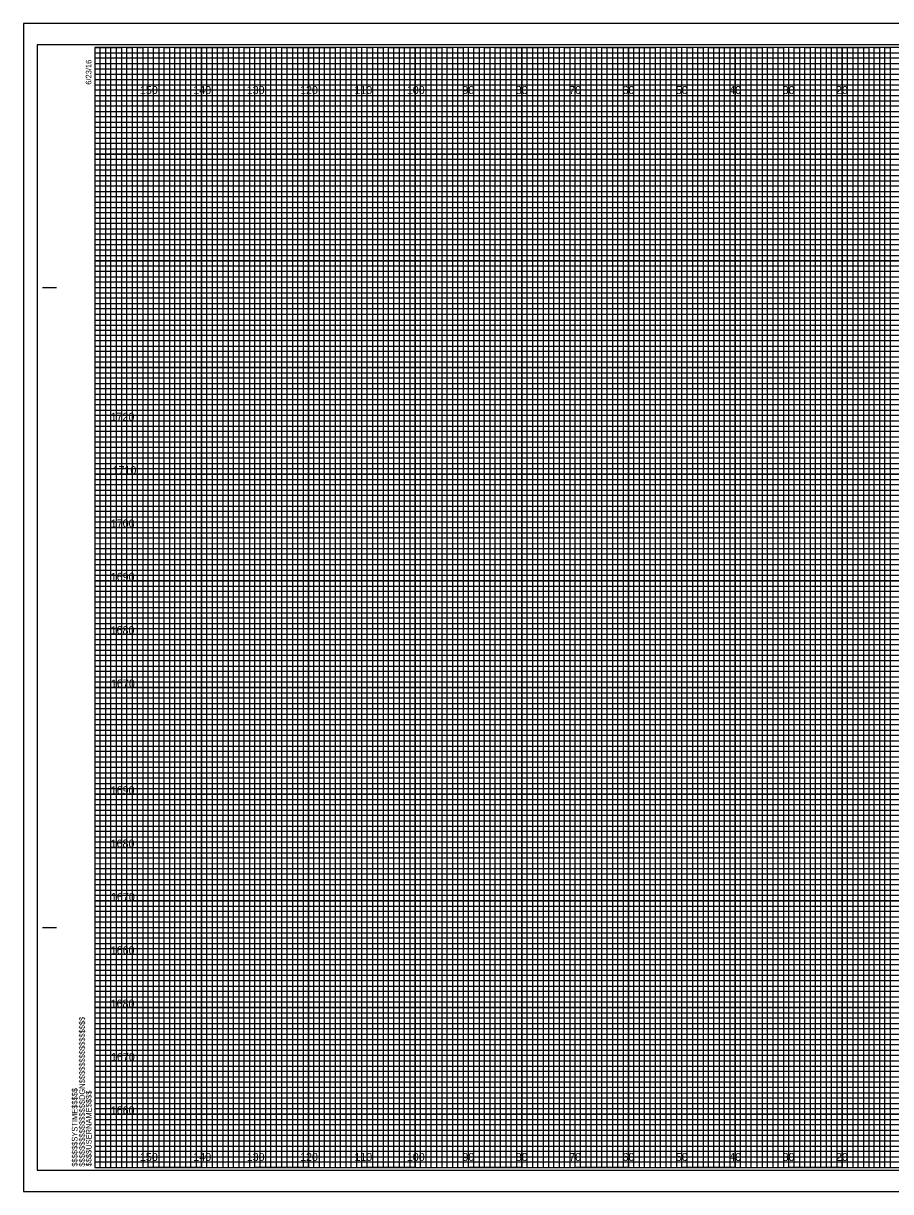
# Model space of a CAD drawing. Extents: x 185 to 522, y -7 to 872.
# Drawn here: x 184.8 to 347.3, y -6.5 to 212.5 of the extents above; entities that cross this region are included whole.
import ezdxf

# ---------------------------------------------------------------- set-up
doc = ezdxf.new("R2010")
doc.units = 0
for name, color, linetype in [('Raster_Level_0', 7, 'Continuous'), ('Scratch_Level_3', 7, 'Continuous'), ('Sheet Cross Section CELL', 7, 'Continuous'), ('Sheet Cross Section Grid Major CELL', 7, 'Continuous'), ('Sheet Cross Section Grid Middle CELL', 7, 'Continuous'), ('Sheet Cross Section Grid Minor 1 CELL', 7, 'Continuous'), ('Sheet Cross Section Grid Minor 2 CELL', 7, 'Continuous'), ('Sheet Cutting Line CELL', 7, 'Continuous'), ('Sheet DOT Grid CELL', 7, 'Continuous'), ('Sheet Plot Border Inside CELL', 7, 'Continuous'), ('Sheet Plot Border Outside CELL', 7, 'Continuous')]:
    doc.layers.add(name, color=color, linetype=linetype)

msp = doc.modelspace()

# ---------------------------------------------------------------- linework, layer by layer
at = {"layer": 'Sheet Cross Section CELL'}
for p, q in [((188.44, 162.95), (190.94, 162.95)), ((188.54, 162.95), (191.04, 162.95)), ((188.44, 42.95), (190.94, 42.95)), ((188.54, 42.95), (191.04, 42.95)), ((198.24, -2.05), (198.24, -2.05)), ((198.24, -2.05), (198.24, -2.05)), ((198.24, -2.05), (198.24, -2.05)), ((198.24, -2.05), (198.24, -2.05)), ((198.24, -2.05), (198.24, -2.05)), ((198.24, -2.05), (198.24, -2.05)), ((198.24, -2.05), (198.24, -2.05))]:
    msp.add_line(p, q, dxfattribs=at)
msp.add_lwpolyline([(518.24, 207.95), (198.24, 207.95), (198.24, -2.05), (518.24, -2.05)], close=True, dxfattribs=at)
at = {"layer": 'Sheet Cross Section Grid Major CELL'}
for p, q in [((208.24, 207.95), (198.24, 207.95)), ((208.24, -2.05), (208.24, 207.95)), ((228.24, 207.95), (218.24, 207.95)), ((218.24, 207.95), (218.24, -2.05)), ((228.24, -2.05), (228.24, 207.95)), ((248.24, 207.95), (238.24, 207.95)), ((238.24, 207.95), (238.24, -2.05)), ((248.24, -2.05), (248.24, 207.95)), ((268.24, 207.95), (258.24, 207.95)), ((258.24, 207.95), (258.24, -2.05)), ((268.24, -2.05), (268.24, 207.95)), ((288.24, 207.95), (278.24, 207.95)), ((278.24, 207.95), (278.24, -2.05)), ((288.24, -2.05), (288.24, 207.95)), ((308.24, 207.95), (298.24, 207.95)), ((298.24, 207.95), (298.24, -2.05)), ((308.24, -2.05), (308.24, 207.95)), ((328.24, 207.95), (318.24, 207.95)), ((318.24, 207.95), (318.24, -2.05)), ((328.24, -2.05), (328.24, 207.95)), ((348.24, 207.95), (338.24, 207.95)), ((338.24, 207.95), (338.24, -2.05)), ((218.24, -2.05), (208.24, -2.05)), ((238.24, -2.05), (228.24, -2.05)), ((258.24, -2.05), (248.24, -2.05)), ((278.24, -2.05), (268.24, -2.05)), ((298.24, -2.05), (288.24, -2.05)), ((318.24, -2.05), (308.24, -2.05)), ((338.24, -2.05), (328.24, -2.05))]:
    msp.add_line(p, q, dxfattribs=at)
for points in [[(198.24, 197.95), (518.24, 197.95), (518.24, 187.95), (198.24, 187.95)], [(198.24, 177.95), (518.24, 177.95), (518.24, 167.95), (198.24, 167.95)], [(198.24, 157.95), (518.24, 157.95), (518.24, 147.95), (198.24, 147.95)], [(198.24, 137.95), (518.24, 137.95), (518.24, 127.95), (198.24, 127.95)], [(198.24, 117.95), (518.24, 117.95), (518.24, 107.95), (198.24, 107.95)], [(198.24, 97.95), (518.24, 97.95), (518.24, 87.95), (198.24, 87.95)], [(198.24, 77.95), (518.24, 77.95), (518.24, 67.95), (198.24, 67.95)], [(198.24, 57.95), (518.24, 57.95), (518.24, 47.95), (198.24, 47.95)], [(198.24, 37.95), (518.24, 37.95), (518.24, 27.95), (198.24, 27.95)], [(198.24, 17.95), (518.24, 17.95), (518.24, 7.95), (198.24, 7.95)]]:
    msp.add_lwpolyline(points, dxfattribs=at)
at = {"layer": 'Sheet Cross Section Grid Middle CELL'}
for points in [[(198.24, 207.95), (203.24, 207.95), (203.24, -2.05), (213.24, -2.05), (213.24, 207.95), (223.24, 207.95), (223.24, -2.05), (233.24, -2.05), (233.24, 207.95), (243.24, 207.95), (243.24, -2.05), (253.24, -2.05), (253.24, 207.95), (263.24, 207.95), (263.24, -2.05), (273.24, -2.05), (273.24, 207.95), (283.24, 207.95), (283.24, -2.05), (293.24, -2.05), (293.24, 207.95), (303.24, 207.95), (303.24, -2.05), (313.24, -2.05), (313.24, 207.95), (323.24, 207.95), (323.24, -2.05), (333.24, -2.05), (333.24, 207.95), (343.24, 207.95), (343.24, -2.05), (353.24, -2.05)], [(198.24, 202.95), (473.24, 202.95)], [(198.24, 182.95), (518.24, 182.95), (518.24, 192.95), (198.24, 192.95)], [(198.24, 162.95), (518.24, 162.95), (518.24, 172.95), (198.24, 172.95)], [(198.24, 142.95), (518.24, 142.95), (518.24, 152.95), (198.24, 152.95)], [(198.24, 122.95), (518.24, 122.95), (518.24, 132.95), (198.24, 132.95)], [(198.24, 102.95), (518.24, 102.95), (518.24, 112.95), (198.24, 112.95)], [(198.24, 82.95), (518.24, 82.95), (518.24, 92.95), (198.24, 92.95)], [(198.24, 62.95), (518.24, 62.95), (518.24, 72.95), (198.24, 72.95)], [(198.24, 42.95), (518.24, 42.95), (518.24, 52.95), (198.24, 52.95)], [(198.24, 22.95), (518.24, 22.95), (518.24, 32.95), (198.24, 32.95)], [(198.24, 2.95), (518.24, 2.95), (518.24, 12.95), (198.24, 12.95)]]:
    msp.add_lwpolyline(points, dxfattribs=at)
at = {"layer": 'Sheet Cross Section Grid Minor 1 CELL'}
for p, q in [((198.24, 206.95), (458.24, 206.95)), ((458.24, 205.93), (198.24, 205.93)), ((198.24, 205.93), (198.24, 204.95)), ((198.24, 204.95), (458.24, 204.95)), ((458.24, 203.84), (198.24, 203.84)), ((198.24, 203.84), (198.24, 201.95)), ((198.24, 201.95), (518.24, 201.95))]:
    msp.add_line(p, q, dxfattribs=at)
for points in [[(198.24, 200.95), (468.24, 200.95), (518.24, 200.95), (518.24, 199.95), (198.24, 199.95)], [(198.24, 198.95), (518.24, 198.95), (518.24, 196.95), (198.24, 196.95)], [(198.24, 195.95), (518.24, 195.95), (518.24, 194.95), (198.24, 194.93)], [(198.24, 193.95), (518.24, 193.95), (518.24, 191.95), (198.24, 191.95)], [(198.24, 190.95), (518.24, 190.95), (518.24, 189.95), (198.24, 189.95)], [(198.24, 188.95), (518.24, 188.95), (518.24, 186.95), (198.24, 186.95)], [(198.24, 185.95), (518.24, 185.95), (518.24, 184.95), (198.24, 184.95)], [(198.24, 183.95), (518.24, 183.95), (518.24, 181.95), (198.24, 181.95)], [(198.24, 180.95), (518.24, 180.95), (518.24, 179.95), (198.24, 179.95)], [(198.24, 178.95), (518.24, 178.95), (518.24, 176.95), (198.24, 176.95)], [(198.24, 175.95), (518.24, 175.95), (518.24, 174.95), (198.24, 174.95)], [(198.24, 173.95), (518.24, 173.95), (518.24, 171.9), (518.24, 170.95), (518.24, 169.95), (198.24, 169.95)], [(198.24, 171.95), (518.24, 171.95), (518.24, 170.95), (198.24, 170.95)], [(198.24, 168.95), (518.24, 168.95), (518.24, 166.95), (198.24, 166.98)], [(198.24, 166.98), (518.24, 166.95), (518.24, 165.95), (198.24, 165.95)], [(198.24, 164.95), (518.24, 164.95), (518.24, 163.95), (198.24, 163.95)], [(198.24, 161.95), (518.24, 161.95), (518.24, 160.95), (198.24, 160.95)], [(198.24, 159.95), (518.24, 159.95), (518.24, 158.95), (198.24, 158.95)], [(198.17, 156.84), (518.24, 156.84), (518.24, 155.83), (198.17, 155.83)], [(198.24, 154.95), (518.24, 154.95), (518.24, 153.95), (198.24, 153.95)], [(198.24, 151.95), (518.24, 151.95), (518.24, 150.95), (198.24, 150.95)], [(198.24, 149.95), (518.24, 149.95), (518.24, 148.95), (198.24, 148.95)], [(198.24, 146.95), (518.24, 146.95), (518.24, 145.95), (198.24, 145.95)], [(198.24, 144.95), (518.24, 144.95), (518.24, 143.95), (198.24, 143.95)], [(198.24, 141.95), (518.24, 141.95), (518.24, 140.95), (198.24, 140.95)], [(198.24, 139.95), (518.24, 139.95), (518.24, 138.95), (198.24, 138.95)], [(198.24, 136.95), (518.24, 136.95), (518.23, 135.93), (198.24, 135.95)], [(198.24, 134.95), (518.24, 134.95), (518.24, 133.95), (198.24, 133.95)], [(198.24, 131.95), (518.24, 131.95), (518.24, 130.95), (198.24, 130.95)], [(198.24, 129.95), (518.24, 129.95), (518.24, 128.95), (198.24, 128.95)], [(198.24, 126.95), (518.24, 126.95), (518.24, 125.95), (198.24, 125.95)], [(198.24, 124.95), (518.24, 124.95), (518.24, 123.95), (198.24, 123.95)], [(198.24, 121.95), (518.24, 121.95), (518.24, 120.95), (198.24, 120.95)], [(198.24, 119.95), (518.24, 119.95), (518.24, 118.95), (198.24, 118.95)], [(198.24, 116.95), (518.24, 116.95), (518.24, 115.95), (198.24, 115.95)], [(198.24, 114.94), (518.31, 114.86), (518.24, 113.95), (198.24, 113.95)], [(198.24, 111.95), (518.24, 111.95), (518.24, 110.95), (198.24, 110.95)], [(198.24, 109.95), (518.24, 109.95), (518.24, 108.95), (198.24, 108.95)], [(198.24, 106.95), (518.24, 106.95), (518.24, 105.95), (198.24, 105.95)], [(198.24, 104.95), (518.24, 104.95), (518.24, 103.95), (198.24, 103.95)], [(198.24, 101.95), (518.24, 101.95), (518.24, 100.95), (198.24, 100.95)], [(198.24, 99.95), (518.24, 99.95), (518.24, 98.95), (198.24, 98.95)], [(198.24, 96.95), (518.24, 96.95), (518.24, 95.95), (198.24, 95.95)], [(198.24, 94.95), (518.24, 94.95), (518.24, 93.95), (198.24, 93.95)], [(198.24, 91.95), (518.24, 91.95), (518.24, 90.95), (198.24, 90.95)], [(198.24, 89.95), (518.24, 89.95), (518.24, 88.95), (198.24, 88.95)], [(198.24, 86.95), (518.24, 86.95), (518.24, 85.95), (198.24, 85.95)], [(198.24, 84.95), (518.24, 84.95), (518.24, 83.95), (198.24, 83.95)], [(198.24, 81.95), (518.24, 81.95), (518.24, 80.95), (198.24, 80.95)], [(198.24, 79.95), (518.24, 79.95), (518.24, 78.95), (198.24, 78.95)], [(198.24, 76.95), (518.24, 76.95), (518.23, 75.93), (198.24, 75.95)], [(198.24, 74.95), (518.24, 74.95), (518.24, 73.95), (198.24, 73.95)], [(198.24, 71.95), (518.24, 71.95), (518.24, 70.95), (198.24, 70.95)], [(198.24, 69.95), (518.24, 69.95), (518.24, 68.95), (198.24, 68.95)], [(198.24, 66.95), (518.24, 66.95), (518.24, 65.95), (198.24, 65.95)], [(198.24, 64.95), (518.24, 64.95), (518.24, 63.95), (198.24, 63.95)], [(198.24, 61.95), (518.24, 61.95), (518.24, 60.95), (198.24, 60.95)], [(198.24, 59.95), (518.24, 59.95), (518.24, 58.95), (198.24, 58.95)], [(198.24, 56.95), (518.24, 56.95), (518.24, 55.95), (198.24, 55.95)], [(198.24, 54.94), (518.31, 54.86), (518.24, 53.95), (198.24, 53.95)], [(198.24, 51.95), (518.24, 51.95), (518.24, 50.95), (198.24, 50.95)], [(198.24, 49.95), (518.24, 49.95), (518.24, 48.95), (198.24, 48.95)], [(198.24, 46.95), (518.24, 46.95), (518.24, 45.95), (198.24, 45.95)], [(198.24, 44.95), (518.24, 44.95), (518.24, 43.95), (198.24, 43.95)], [(198.24, 41.95), (518.24, 41.95), (518.24, 40.95), (198.24, 40.95)], [(198.24, 39.95), (518.24, 39.95), (518.24, 38.95), (198.24, 38.95)], [(198.24, 36.95), (518.24, 36.95), (518.24, 35.95), (198.24, 35.95)], [(198.24, 34.95), (518.24, 34.95), (518.24, 33.95), (198.24, 33.95)], [(198.24, 31.95), (518.24, 31.95), (518.24, 30.95), (198.24, 30.95)], [(198.24, 29.95), (518.24, 29.95), (518.24, 28.95), (198.24, 28.95)], [(198.24, 26.95), (518.24, 26.95), (518.24, 25.95), (198.24, 25.95)], [(198.24, 24.95), (518.24, 24.95), (518.24, 23.95), (198.24, 23.95)], [(198.24, 21.95), (518.24, 21.95), (518.24, 20.95), (198.24, 20.95)], [(198.24, 19.95), (518.24, 19.95), (518.24, 18.95), (198.24, 18.95)], [(198.24, 16.95), (518.24, 16.95), (518.24, 15.95), (198.24, 15.95)], [(198.24, 14.95), (518.24, 14.95), (518.24, 13.95), (198.24, 13.95)], [(198.24, 11.95), (518.24, 11.95), (518.24, 10.95), (198.24, 10.95)], [(198.24, 9.95), (518.24, 9.95), (518.24, 8.95), (198.24, 8.95)], [(198.24, 6.95), (518.24, 6.95), (518.24, 5.95), (198.24, 5.95)], [(198.24, 4.95), (518.24, 4.95), (518.24, 3.95), (198.24, 3.95)], [(198.24, 1.95), (518.24, 1.95), (518.24, 0.95), (198.24, 0.95)], [(198.24, -0.05), (518.24, -0.05), (518.24, -1.05), (198.24, -1.05)]]:
    msp.add_lwpolyline(points, dxfattribs=at)
at = {"layer": 'Sheet Cross Section Grid Minor 2 CELL'}
for points in [[(198.24, -2.05), (199.24, -2.05), (199.24, 207.95), (200.24, 207.95), (200.24, -2.05)], [(200.24, -2.05), (201.24, -2.05), (201.24, 207.95), (202.24, 207.95), (202.24, -2.05)], [(203.24, -2.05), (204.24, -2.05), (204.24, 207.95), (205.24, 207.95), (205.24, -2.05)], [(205.24, -2.05), (206.24, -2.05), (206.24, 207.95), (207.24, 207.95), (207.24, -2.05)], [(208.24, -2.05), (209.24, -2.05), (209.24, 207.95), (210.24, 207.95), (210.24, -2.05)], [(210.24, -2.05), (211.24, -2.05), (211.24, 207.95), (212.24, 207.95), (212.24, -2.05)], [(213.24, -2.05), (214.24, -2.05), (214.24, 207.95), (215.24, 207.95), (215.24, -2.05)], [(215.24, -2.05), (216.24, -2.05), (216.24, 207.95), (217.24, 207.95), (217.24, -2.05)], [(218.24, -2.05), (219.24, -2.05), (219.24, 207.95), (220.24, 207.95), (220.24, -2.05)], [(220.24, -2.05), (221.24, -2.05), (221.24, 207.95), (222.24, 207.95), (222.24, -2.05)], [(223.24, -2.05), (224.24, -2.05), (224.24, 207.95), (225.24, 207.95), (225.24, -2.05)], [(225.24, -2.05), (226.24, -2.05), (226.24, 207.95), (227.24, 207.95), (227.24, -2.05)], [(228.24, -2.05), (229.24, -2.05), (229.24, 207.95), (230.24, 207.95), (230.24, -2.05)], [(230.24, -2.05), (231.24, -2.05), (231.24, 207.95), (232.24, 207.95), (232.24, -2.05)], [(233.24, -2.05), (234.24, -2.05), (234.24, 207.95), (235.24, 207.95), (235.24, -2.05)], [(235.24, -2.05), (236.24, -2.05), (236.24, 207.95), (237.24, 207.95), (237.24, -2.05)], [(238.24, -2.05), (239.24, -2.05), (239.24, 207.95), (240.24, 207.95), (240.24, -2.05)], [(240.24, -2.05), (241.24, -2.05), (241.24, 207.95), (242.24, 207.95), (242.24, -2.05)], [(243.24, -2.05), (244.24, -2.05), (244.24, 207.95), (245.24, 207.95), (245.24, -2.05)], [(245.24, -2.05), (246.24, -2.05), (246.24, 207.95), (247.24, 207.95), (247.24, -2.05)], [(248.24, -2.05), (249.24, -2.05), (249.24, 207.95), (250.24, 207.95), (250.24, -2.05)], [(250.24, -2.05), (251.24, -2.05), (251.24, 207.95), (252.24, 207.95), (252.24, -2.05)], [(253.24, -2.05), (254.24, -2.05), (254.24, 207.95), (255.24, 207.95), (255.24, -2.05)], [(255.24, -2.05), (256.24, -2.05), (256.24, 207.95), (257.24, 207.95), (257.24, -2.05)], [(258.24, -2.05), (259.24, -2.05), (259.24, 207.95), (260.24, 207.95), (260.24, -2.05)], [(260.24, -2.05), (261.24, -2.05), (261.24, 207.95), (262.24, 207.95), (262.24, -2.05)], [(263.24, -2.05), (264.24, -2.05), (264.24, 207.95), (265.24, 207.95), (265.24, -2.05)], [(265.24, -2.05), (266.24, -2.05), (266.24, 207.95), (267.24, 207.95), (267.24, -2.05)], [(268.24, -2.05), (269.24, -2.05), (269.24, 207.95), (270.24, 207.95), (270.24, -2.05)], [(270.24, -2.05), (271.24, -2.05), (271.24, 207.95), (272.24, 207.95), (272.24, -2.05)], [(273.24, -2.05), (274.24, -2.05), (274.24, 207.95), (275.24, 207.95), (275.24, -2.05)], [(275.24, -2.05), (276.24, -2.05), (276.24, 207.95), (277.24, 207.95), (277.24, -2.05)], [(278.24, -2.05), (279.24, -2.05), (279.24, 207.95), (280.24, 207.95), (280.24, -2.05)], [(280.24, -2.05), (281.24, -2.05), (281.24, 207.95), (282.24, 207.95), (282.24, -2.05)], [(283.24, -2.05), (284.24, -2.05), (284.24, 207.95), (285.24, 207.95), (285.24, -2.05)], [(285.24, -2.05), (286.24, -2.05), (286.24, 207.95), (287.24, 207.95), (287.24, -2.05)], [(288.24, -2.05), (289.24, -2.05), (289.24, 207.95), (290.24, 207.95), (290.24, -2.05)], [(290.24, -2.05), (291.24, -2.05), (291.24, 207.95), (292.24, 207.95), (292.24, -2.05)], [(293.24, -2.05), (294.24, -2.05), (294.24, 207.95), (295.24, 207.95), (295.24, -2.05)], [(295.24, -2.05), (296.24, -2.05), (296.24, 207.95), (297.24, 207.95), (297.24, -2.05)], [(298.24, -2.05), (299.24, -2.05), (299.24, 207.95), (300.24, 207.95), (300.24, -2.05)], [(300.24, -2.05), (301.24, -2.05), (301.24, 207.95), (302.24, 207.95), (302.24, -2.05)], [(303.24, -2.05), (304.24, -2.05), (304.24, 207.95), (305.24, 207.95), (305.24, -2.05)], [(305.24, -2.05), (306.24, -2.05), (306.24, 207.95), (307.24, 207.95), (307.24, -2.05)], [(308.24, -2.05), (309.24, -2.05), (309.24, 207.95), (310.24, 207.95), (310.24, -2.05)], [(310.24, -2.05), (311.24, -2.05), (311.24, 207.95), (312.24, 207.95), (312.24, -2.05)], [(313.24, -2.05), (314.24, -2.05), (314.24, 207.95), (315.24, 207.95), (315.24, -2.05)], [(315.24, -2.05), (316.24, -2.05), (316.24, 207.95), (317.24, 207.95), (317.24, -2.05)], [(318.24, -2.05), (319.24, -2.05), (319.24, 207.95), (320.24, 207.95), (320.24, -2.05)], [(320.24, -2.05), (321.24, -2.05), (321.24, 207.95), (322.24, 207.95), (322.24, -2.05)], [(323.24, -2.05), (324.24, -2.05), (324.24, 207.95), (325.24, 207.95), (325.24, -2.05)], [(325.24, -2.05), (326.24, -2.05), (326.24, 207.95), (327.24, 207.95), (327.24, -2.05)], [(328.24, -2.05), (329.24, -2.05), (329.24, 207.95), (330.24, 207.95), (330.24, -2.05)], [(330.24, -2.05), (331.24, -2.05), (331.24, 207.95), (332.24, 207.95), (332.24, -2.05)], [(333.24, -2.05), (334.24, -2.05), (334.24, 207.95), (335.24, 207.95), (335.24, -2.05)], [(335.24, -2.05), (336.24, -2.05), (336.24, 207.95), (337.24, 207.95), (337.24, -2.05)], [(338.24, -2.05), (339.24, -2.05), (339.24, 207.95), (340.24, 207.95), (340.24, -2.05)], [(340.24, -2.05), (341.24, -2.05), (341.24, 207.95), (342.24, 207.95), (342.24, -2.05)], [(343.24, -2.05), (344.24, -2.05), (344.24, 207.95), (345.24, 207.95), (345.24, -2.05)], [(345.24, -2.05), (346.24, -2.05), (346.24, 207.95), (347.24, 207.95), (347.24, -2.05)]]:
    msp.add_lwpolyline(points, dxfattribs=at)
at = {"layer": 'Sheet Cutting Line CELL'}
for p, q in [((521.54, 212.45), (184.84, 212.45)), ((184.84, 212.45), (184.84, -6.55)), ((184.84, -6.55), (521.54, -6.55))]:
    msp.add_line(p, q, dxfattribs=at)
at = {"layer": 'Sheet DOT Grid CELL'}
for p, q in [((208.24, -2.05), (208.24, 207.95)), ((218.24, -2.05), (218.24, 207.95)), ((228.24, -2.05), (228.24, 207.95)), ((238.24, -2.05), (238.24, 207.95)), ((248.24, -2.05), (248.24, 207.95)), ((258.24, -2.05), (258.24, 207.95)), ((268.24, -2.05), (268.24, 207.95)), ((278.24, -2.05), (278.24, 207.95)), ((288.24, -2.05), (288.24, 207.95)), ((298.24, -2.05), (298.24, 207.95)), ((308.24, -2.05), (308.24, 207.95)), ((318.24, -2.05), (318.24, 207.95)), ((328.24, -2.05), (328.24, 207.95)), ((338.24, -2.05), (338.24, 207.95)), ((198.24, 197.95), (518.24, 197.95)), ((198.24, 187.95), (518.24, 187.95)), ((198.24, 177.95), (518.24, 177.95)), ((198.24, 167.95), (518.24, 167.95)), ((198.24, 157.95), (518.24, 157.95)), ((198.24, 147.95), (518.24, 147.95)), ((198.24, 137.95), (518.24, 137.95)), ((198.24, 127.95), (518.24, 127.95)), ((198.24, 117.95), (518.24, 117.95)), ((198.24, 107.95), (518.24, 107.95)), ((198.24, 97.95), (518.24, 97.95)), ((198.24, 87.95), (518.24, 87.95)), ((198.24, 77.95), (518.24, 77.95)), ((198.24, 67.95), (518.24, 67.95)), ((198.24, 57.95), (518.24, 57.95)), ((198.24, 47.95), (518.24, 47.95)), ((198.24, 37.95), (518.24, 37.95)), ((198.24, 27.95), (518.24, 27.95)), ((198.24, 17.95), (518.24, 17.95)), ((198.24, 7.95), (518.24, 7.95))]:
    msp.add_line(p, q, dxfattribs=at)
at = {"layer": 'Sheet Plot Border Inside CELL'}
msp.add_lwpolyline([(187.44, -2.55), (520.64, -2.55), (520.64, 208.45), (187.44, 208.45)], close=True, dxfattribs=at)
at = {"layer": 'Sheet Plot Border Outside CELL'}
msp.add_lwpolyline([(184.84, -6.55), (521.54, -6.55), (521.54, 212.45), (184.84, 212.45)], close=True, dxfattribs=at)

# ---------------------------------------------------------------- texts
at = {"layer": 'Raster_Level_0'}
for s, p in [('150', (206.69, 199.2)), ('140', (216.69, 199.2)), ('130', (226.69, 199.2)), ('120', (236.69, 199.2)), ('110', (246.87, 199.2)), ('100', (256.69, 199.2)), ('90', (267.1, 199.2)), ('80', (277.1, 199.2)), ('70', (287.1, 199.2)), ('60', (297.1, 199.2)), ('50', (307.1, 199.2)), ('40', (317.1, 199.2)), ('30', (327.1, 199.2)), ('20', (337.1, 199.2)), ('150', (206.69, -0.8)), ('140', (216.69, -0.8)), ('130', (226.69, -0.8)), ('120', (236.69, -0.8)), ('110', (246.87, -0.8)), ('100', (256.69, -0.8)), ('90', (267.1, -0.8)), ('80', (277.1, -0.8)), ('70', (287.1, -0.8)), ('60', (297.1, -0.8)), ('50', (307.1, -0.8)), ('40', (317.1, -0.8)), ('30', (327.1, -0.8)), ('20', (337.1, -0.8))]:
    msp.add_text(s, height=1.5, dxfattribs=at).set_placement(p)
at = {"layer": 'Scratch_Level_3'}
for s, p in [('1720', (201.18, 137.95)), ('1710', (201.55, 127.95)), ('1700', (201.22, 117.95)), ('1690', (201.21, 107.95)), ('1680', (201.19, 97.95)), ('1670', (201.25, 87.95)), ('1690', (201.21, 67.95)), ('1680', (201.19, 57.95)), ('1670', (201.25, 47.95)), ('1660', (201.21, 37.95)), ('1680', (201.19, 27.95)), ('1670', (201.25, 17.95)), ('1660', (201.21, 7.95))]:
    msp.add_text(s, height=1.5, dxfattribs=at).set_placement(p)
at = {"layer": 'Sheet Cross Section CELL'}
for s, p in [('6/23/16', (197.59, 200.95)), ('$$$$$$$$$$$$$$$$DGN$$$$$$$$$$$$$$$$', (196.36, -1.87)), ('$$$$$$SYSTIME$$$$$', (194.98, -1.87)), ('$$$$USERNAME$$$$', (197.62, -1.82))]:
    msp.add_text(s, height=1.05, rotation=90, dxfattribs=at).set_placement(p)

doc.saveas('drawing.dxf')
